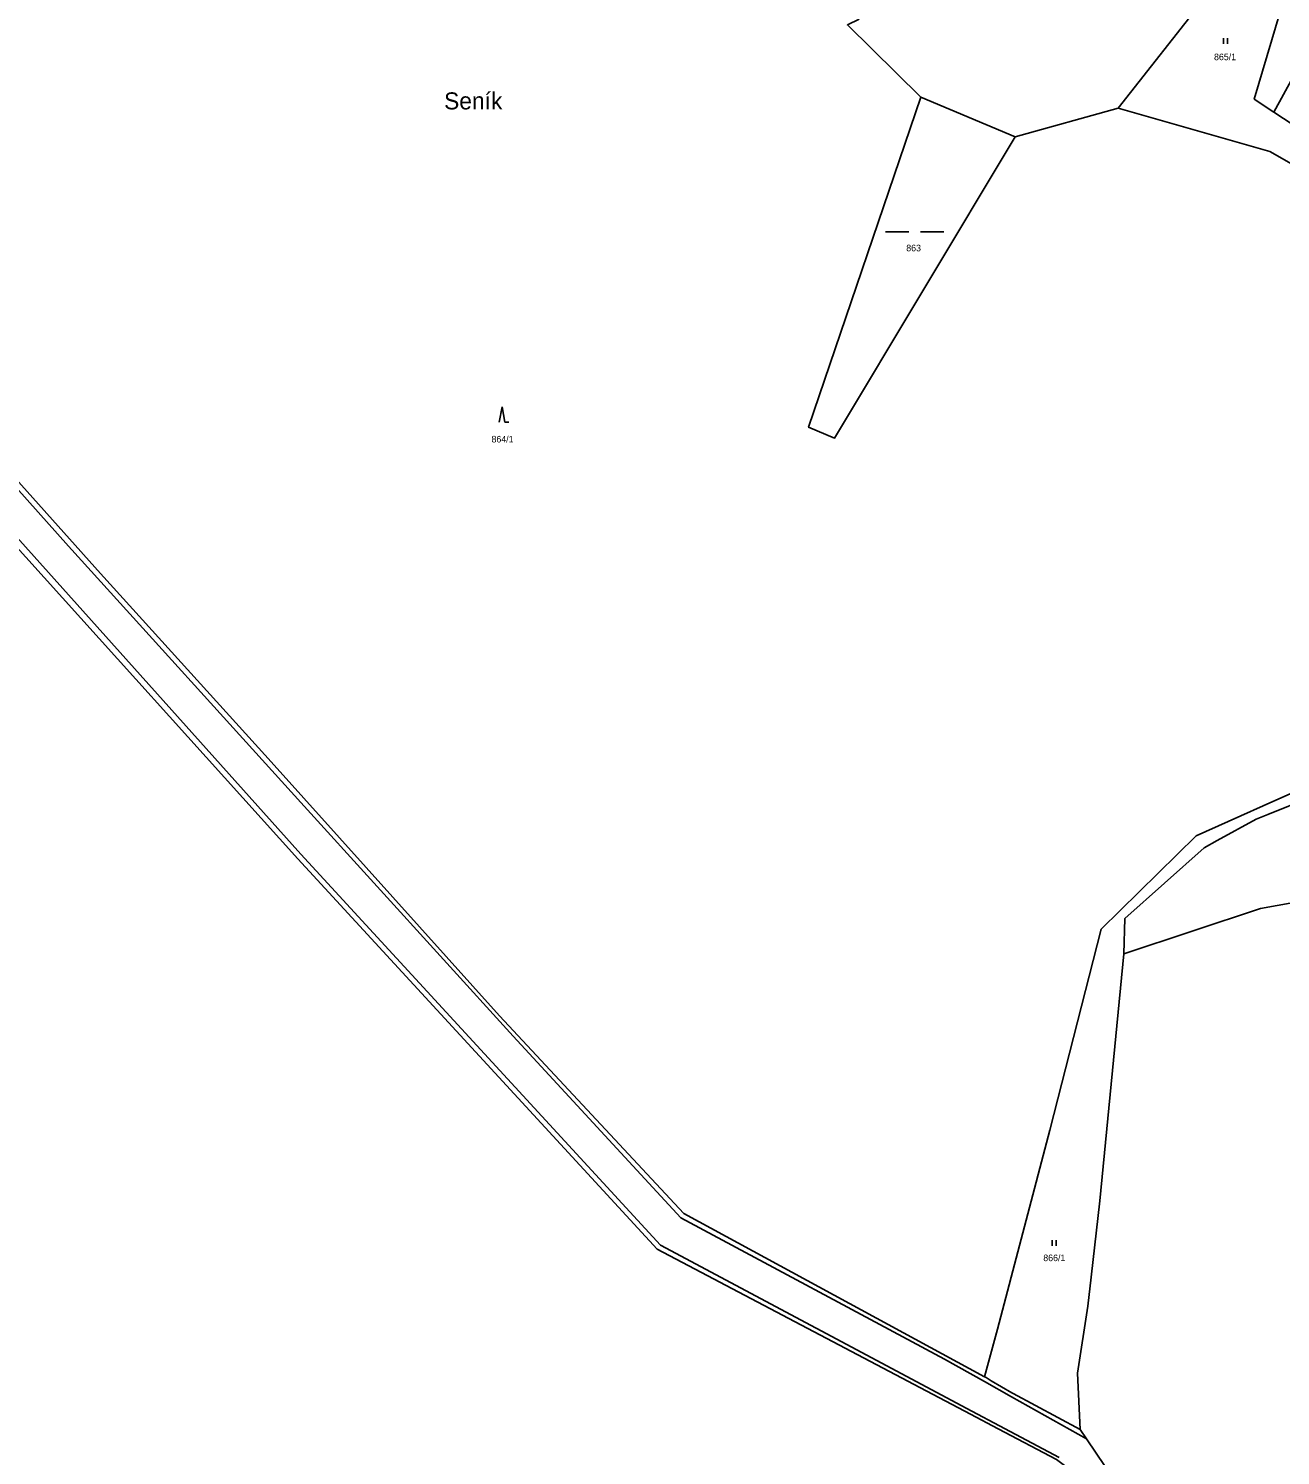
# Model space of a CAD drawing. Extents: x -751333 to -746055, y -1133395 to -1129777.
# Drawn here: x -747546.5 to -747223.3, y -1132233.4 to -1131865 of the extents above; entities that cross this region are included whole.
import ezdxf

# ---------------------------------------------------------------- set-up
doc = ezdxf.new("R2010")
doc.units = 0
for name, color, linetype in [('Hranice parcel', 7, 'Continuous'), ('Parcelní čísla', 7, 'Continuous'), ('Pop  PČ popisy', 7, 'Continuous'), ('Vnitřní kresba', 7, 'Continuous'), ('Značky kultur', 7, 'Continuous')]:
    doc.layers.add(name, color=color, linetype=linetype)

msp = doc.modelspace()

# ---------------------------------------------------------------- linework, layer by layer
at = {"layer": 'Hranice parcel'}
for p, q in [((-747224.99, -1131886.58), (-747166.79, -1131779.35)), ((-747223.51, -1131832.44), (-747265.2, -1131885.54)), ((-747291.78, -1131892.94), (-747316.12, -1131882.74)), ((-747265.2, -1131885.54), (-747291.78, -1131892.94)), ((-747220.07, -1131889.85), (-747224.99, -1131886.58)), ((-747263.75, -1132103.85), (-747228.47, -1132092.15)), ((-747269.98, -1132167.65), (-747263.75, -1132103.85)), ((-747272.17, -1132187.34), (-747269.98, -1132167.65)), ((-747273, -1132194.85), (-747272.17, -1132187.34))]:
    msp.add_line(p, q, dxfattribs=at)
for points in [[(-747224.99, -1131886.58), (-747230.08, -1131883.19), (-747216.68, -1131837.99), (-747213.89, -1131810.39), (-747211.65, -1131788.43)], [(-747316.12, -1131882.74), (-747335.11, -1131864.05), (-747332.1, -1131862.53)], [(-747677.59, -1131870.17), (-747657.84, -1131883.3), (-747627.77, -1131904.51), (-747602.54, -1131922.38), (-747575.35, -1131952.76), (-747527.98, -1132005.67), (-747484.7, -1132053.47), (-747466.25, -1132073.95), (-747424.9, -1132119.88), (-747377.31, -1132170.88), (-747299.75, -1132213.05)], [(-747258.19, -1132251.66), (-747281.16, -1132234.43), (-747296.21, -1132226.5), (-747303.31, -1132222.76), (-747384.2, -1132180.15), (-747476.98, -1132079.32), (-747551.95, -1131996.25), (-747608.69, -1131932.57), (-747681.55, -1131879.32), (-747717.34, -1131873.06)], [(-747316.12, -1131882.74), (-747345.14, -1131967.94), (-747338.44, -1131970.72), (-747291.78, -1131892.94)], [(-747072.89, -1131966.47), (-747107.18, -1131952.81), (-747140.46, -1131946.56), (-747154.1, -1131938.56), (-747161.04, -1131934.49), (-747204.18, -1131909.18), (-747226.07, -1131896.73), (-747265.2, -1131885.54)], [(-747299.75, -1132213.05), (-747296.34, -1132200.82), (-747282.88, -1132149.41), (-747269.58, -1132097.49), (-747245.11, -1132073.4), (-747236.79, -1132069.7), (-747224.47, -1132064.21), (-747203.37, -1132054.82), (-747145.49, -1132044.7), (-747109.66, -1132039.16), (-747102.43, -1132037.5)], [(-747263.75, -1132103.85), (-747263.48, -1132094.73), (-747243.01, -1132076.52), (-747239.61, -1132074.64), (-747229.58, -1132069.12), (-747226.57, -1132067.9), (-747204.37, -1132058.93), (-747184.23, -1132054.46), (-747152.75, -1132049.88), (-747102.63, -1132042.55), (-747054.35, -1132037.66)], [(-747228.47, -1132092.15), (-747166.2, -1132081.01), (-747144.88, -1132077.08), (-747120.33, -1132072.66)], [(-747275.02, -1132226.71), (-747275.71, -1132212.14), (-747273, -1132194.85)], [(-747299.75, -1132213.05), (-747299.33, -1132213.3), (-747297.97, -1132214.09), (-747292.64, -1132217.19), (-747292.36, -1132217.35), (-747275.02, -1132226.71)], [(-747258.19, -1132251.66), (-747259.29, -1132250.03), (-747273.4, -1132229.11), (-747275.02, -1132226.71)]]:
    msp.add_lwpolyline(points, dxfattribs=at)
at = {"layer": 'Vnitřní kresba'}
for p, q in [((-747536.19, -1131998.64), (-747603.28, -1131923.51)), ((-747476.22, -1132078.18), (-747608.07, -1131931.1)), ((-747475.41, -1132065.78), (-747536.19, -1131998.64)), ((-747421.42, -1132125.12), (-747475.41, -1132065.78)), ((-747383.4, -1132179.12), (-747476.22, -1132078.18)), ((-747378.09, -1132172.01), (-747421.42, -1132125.12)), ((-747310.05, -1132208.51), (-747378.09, -1132172.01)), ((-747302.97, -1132221.96), (-747383.4, -1132179.12)), ((-747299.75, -1132214.3), (-747310.05, -1132208.51)), ((-747299.75, -1132214.3), (-747292.78, -1132218.26)), ((-747292.78, -1132218.26), (-747273.4, -1132229.11)), ((-747295.89, -1132225.73), (-747302.97, -1132221.96)), ((-747280.48, -1132233.94), (-747295.89, -1132225.73))]:
    msp.add_line(p, q, dxfattribs=at)
at = {"layer": 'Značky kultur'}
for p, q in [((-747238.011, -1131868.93), (-747238.011, -1131867.43)), ((-747237.01, -1131868.93), (-747237.01, -1131867.43)), ((-747325.239, -1131917.45), (-747319.239, -1131917.45)), ((-747316.239, -1131917.45), (-747310.239, -1131917.45)), ((-747424.27, -1131962.65), (-747425.02, -1131966.65)), ((-747423.52, -1131966.65), (-747424.27, -1131962.65)), ((-747423.52, -1131966.65), (-747422.524, -1131966.65)), ((-747282.251, -1132179.3), (-747282.251, -1132177.8)), ((-747281.25, -1132179.3), (-747281.25, -1132177.8))]:
    msp.add_line(p, q, dxfattribs=at)

# ---------------------------------------------------------------- texts
at = {"layer": 'Parcelní čísla'}
for s, p in [('865/1', (-747240.46, -1131873.15)), ('863', (-747319.92, -1131922.49)), ('864/1', (-747427, -1131971.85)), ('866/1', (-747284.54, -1132183.22))]:
    msp.add_text(s, height=1.7, dxfattribs=at).set_placement(p)
at = {"layer": 'Pop  PČ popisy'}
msp.add_text('Seník', height=4.4, dxfattribs=at).set_placement((-747439.243, -1131885.86))

doc.saveas('drawing.dxf')
